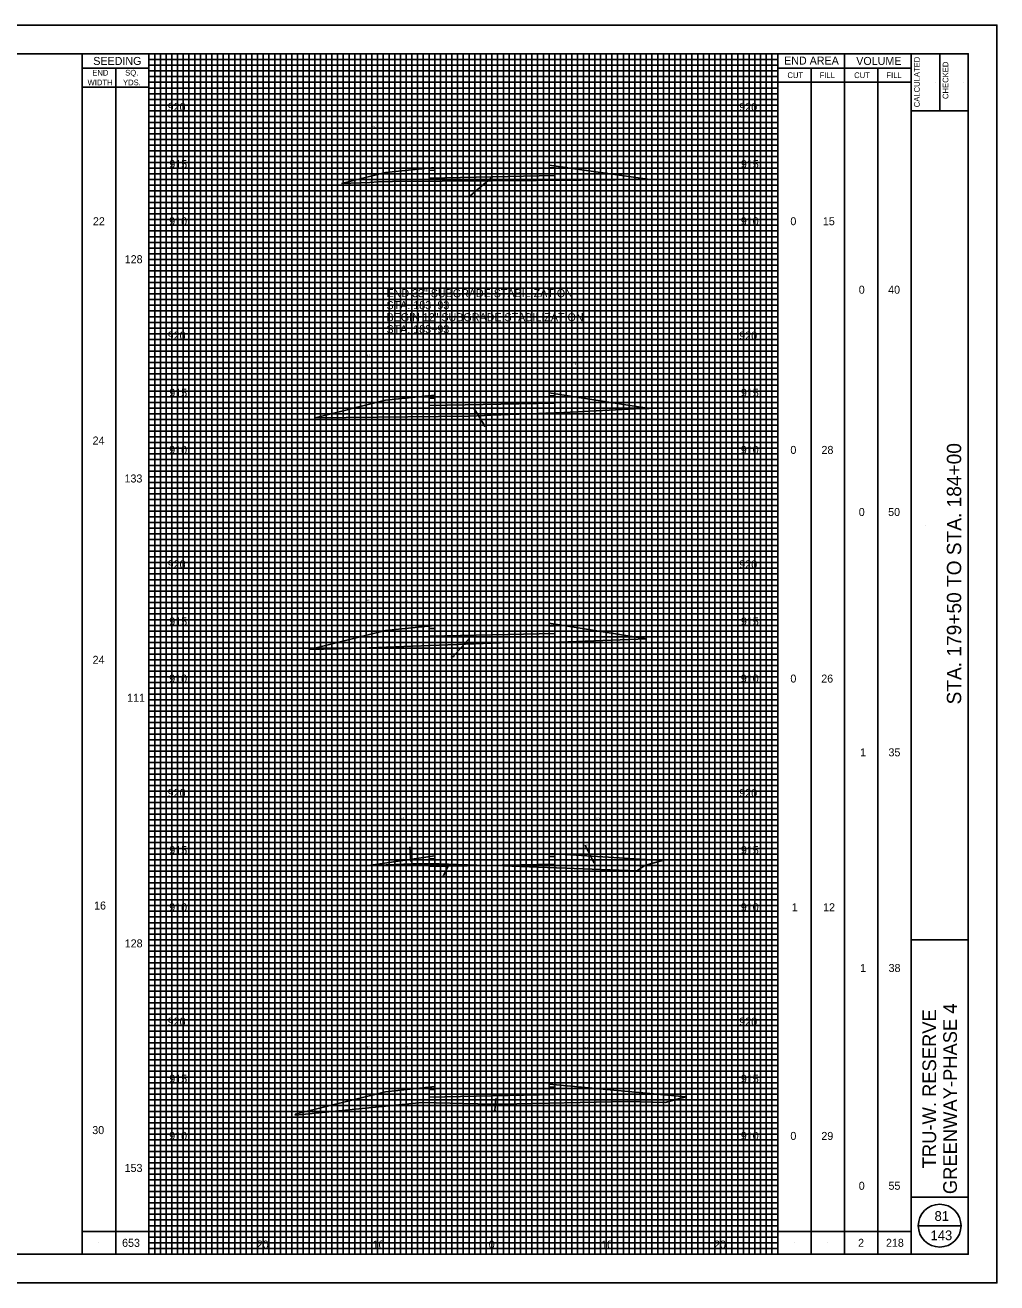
# Model space of a CAD drawing. Extents: x -73 to 160, y -2 to 1877.
# Drawn here: x 75 to 160, y 802.5 to 912.5 of the extents above; entities that cross this region are included whole.
import ezdxf

# ---------------------------------------------------------------- set-up
doc = ezdxf.new("R2010")
doc.units = 0
for name, color, linetype in [('DR_P_Flood_Boundary', 7, 'Continuous'), ('GK_Cells', 7, 'Continuous'), ('RD_X_Fence', 7, 'Continuous'), ('TX_X_5', 7, 'Continuous'), ('UT_P_Water_Cells', 7, 'Continuous'), ('XS_P_Pavt_Layers', 7, 'Continuous'), ('XS_P_Pavt_Surface', 7, 'Continuous'), ('XS_X_Ground_Line', 7, 'Continuous')]:
    doc.layers.add(name, color=color, linetype=linetype)

msp = doc.modelspace()

# ---------------------------------------------------------------- linework, layer by layer
at = {"layer": 'DR_P_Flood_Boundary'}
for p, q in [((90.83, 805), (90.83, 910)), ((95.83, 805), (95.83, 910)), ((100.83, 805), (100.83, 910)), ((105.83, 805), (105.83, 910)), ((110.83, 805), (110.83, 910)), ((115.83, 805), (115.83, 910)), ((120.83, 805), (120.83, 910)), ((125.83, 805), (125.83, 910)), ((130.83, 805), (130.83, 910)), ((135.83, 805), (135.83, 910)), ((85.83, 905), (140.83, 905)), ((85.83, 900), (140.83, 900)), ((85.83, 895), (140.83, 895)), ((85.83, 890), (140.83, 890)), ((85.83, 885), (140.83, 885)), ((85.83, 880), (140.83, 880)), ((85.83, 875), (140.83, 875)), ((85.83, 870), (140.83, 870)), ((85.83, 865), (140.83, 865)), ((85.83, 860), (140.83, 860)), ((85.83, 855), (140.83, 855)), ((85.83, 850), (140.83, 850)), ((85.83, 845), (140.83, 845)), ((85.83, 840), (140.83, 840)), ((85.83, 835), (140.83, 835)), ((85.83, 830), (140.83, 830)), ((85.83, 825), (140.83, 825)), ((85.83, 820), (140.83, 820)), ((85.83, 815), (140.83, 815)), ((85.83, 810), (140.83, 810))]:
    msp.add_line(p, q, dxfattribs=at)
at = {"layer": 'GK_Cells'}
for p, q in [((152.5, 805), (152.5, 910)), ((155, 910), (155, 905)), ((152.5, 905), (157.5, 905)), ((152.5, 832.5), (157.5, 832.5)), ((152.5, 810), (157.5, 810))]:
    msp.add_line(p, q, dxfattribs=at)
msp.add_lwpolyline([(0, 910), (157.5, 910), (157.5, 805), (0, 805)], close=True, dxfattribs=at)
at = {"layer": 'RD_X_Fence'}
for p, q in [((110.83, 900.06), (106.51, 899.61)), ((110.33, 899.8), (110.83, 899.81)), ((129.65, 899), (120.83, 900.26)), ((120.83, 900.01), (121.33, 900.02)), ((121.33, 900.02), (121.33, 899.35)), ((106.51, 899.61), (102.66, 898.65)), ((110.33, 899.13), (110.33, 899.8)), ((121.33, 899.35), (110.33, 899.13)), ((115.9, 899.25), (113.92, 897.58)), ((110.83, 880.14), (106.51, 879.7)), ((129.6, 878.96), (120.83, 880.34)), ((120.83, 880.09), (121.33, 880.1)), ((121.33, 880.1), (121.33, 879.44)), ((106.51, 879.7), (100.37, 878.16)), ((110.33, 879.88), (110.83, 879.89)), ((110.33, 879.22), (110.33, 879.88)), ((121.33, 879.44), (110.33, 879.22)), ((114.26, 878.99), (115.24, 877.41)), ((106.51, 859.55), (99.88, 857.89)), ((110.83, 859.99), (106.51, 859.55)), ((110.33, 859.73), (110.83, 859.74)), ((110.33, 859.07), (110.33, 859.73)), ((121.33, 859.29), (110.33, 859.07)), ((129.36, 858.83), (120.83, 860.19)), ((120.83, 859.94), (121.33, 859.95)), ((121.33, 859.95), (121.33, 859.29)), ((113.88, 858.88), (112.42, 857.25)), ((108.73, 839.35), (108.65, 840.6)), ((124.77, 839.22), (124, 840.79)), ((110.83, 839.84), (105.03, 839.01)), ((110.33, 839.58), (110.83, 839.59)), ((110.33, 839.16), (110.33, 839.58)), ((130.73, 839.44), (120.83, 840.04)), ((120.83, 840.04), (120.83, 839.93)), ((120.83, 839.93), (120.83, 839.79)), ((120.83, 839.79), (121.33, 839.8)), ((121.33, 839.8), (121.33, 839.13)), ((110.33, 839.16), (110.33, 838.91)), ((110.33, 838.91), (115.34, 839.01)), ((112.03, 839.03), (111.6, 838.1)), ((121.33, 839.13), (116.73, 839.04)), ((116.73, 839.04), (116.79, 838.98)), ((110.83, 819.67), (106.51, 819.22)), ((132.8, 818.77), (120.83, 819.87)), ((120.83, 819.62), (121.33, 819.63)), ((121.33, 819.63), (121.33, 818.96)), ((106.51, 819.22), (98.62, 817.25)), ((110.33, 819.41), (110.83, 819.42)), ((110.33, 818.74), (110.33, 819.41)), ((121.33, 818.96), (110.33, 818.74)), ((116.17, 818.62), (116.09, 817.56))]:
    msp.add_line(p, q, dxfattribs=at)
for points in [[(110.83, 899.81), (110.83, 899.95), (110.83, 900.06)], [(120.83, 900.26), (120.83, 900.15), (120.83, 900.01)], [(102.66, 898.65), (105.14, 898.74), (105.88, 898.8), (107.13, 898.82), (115.83, 898.88), (123.61, 898.94), (129.65, 899)], [(110.83, 879.89), (110.83, 880.04), (110.83, 880.14)], [(120.83, 880.34), (120.83, 880.24), (120.83, 880.09)], [(100.37, 878.16), (113.88, 878.3), (115.83, 878.38), (122.11, 878.63), (128.32, 878.95), (129.6, 878.96)], [(110.83, 859.74), (110.83, 859.89), (110.83, 859.99)], [(120.83, 860.19), (120.83, 860.09), (120.83, 859.94)], [(99.88, 857.89), (103.52, 857.98), (115.83, 858.45), (118.07, 858.54), (120.92, 858.51), (129.36, 858.83)], [(110.83, 839.59), (110.83, 839.73), (110.83, 839.84)], [(116.79, 838.98), (128.51, 838.53), (129.22, 838.99), (130.73, 839.44)], [(105.03, 839.01), (108.89, 839.15), (110.33, 839.16)], [(115.34, 839.01), (111.23, 839.16), (110.33, 839.16)], [(110.83, 819.42), (110.83, 819.56), (110.83, 819.67)], [(120.83, 819.87), (120.83, 819.76), (120.83, 819.62)], [(98.65, 817.16), (109.72, 818.27), (115.83, 818.13), (116.62, 818.12), (127.71, 818.37), (130.99, 818.26), (132.8, 818.77)], [(98.62, 817.25), (98.65, 817.16)]]:
    msp.add_lwpolyline(points, dxfattribs=at)
at = {"layer": 'TX_X_5'}
msp.add_lwpolyline([(-10, 802.5), (160, 802.5), (160, 912.5), (-10, 912.5)], close=True, dxfattribs=at)
at = {"layer": 'UT_P_Water_Cells'}
for p, q in [((86.33, 805), (86.33, 910)), ((86.83, 805), (86.83, 910)), ((87.33, 805), (87.33, 910)), ((87.83, 805), (87.83, 910)), ((88.33, 805), (88.33, 910)), ((88.83, 805), (88.83, 910)), ((89.33, 805), (89.33, 910)), ((89.83, 805), (89.83, 910)), ((90.33, 805), (90.33, 910)), ((91.33, 805), (91.33, 910)), ((91.83, 805), (91.83, 910)), ((92.33, 805), (92.33, 910)), ((92.83, 805), (92.83, 910)), ((93.33, 805), (93.33, 910)), ((93.83, 805), (93.83, 910)), ((94.33, 805), (94.33, 910)), ((94.83, 805), (94.83, 910)), ((95.33, 805), (95.33, 910)), ((96.33, 805), (96.33, 910)), ((96.83, 805), (96.83, 910)), ((97.33, 805), (97.33, 910)), ((97.83, 805), (97.83, 910)), ((98.33, 805), (98.33, 910)), ((98.83, 805), (98.83, 910)), ((99.33, 805), (99.33, 910)), ((99.83, 805), (99.83, 910)), ((100.33, 805), (100.33, 910)), ((101.33, 805), (101.33, 910)), ((101.83, 805), (101.83, 910)), ((102.33, 805), (102.33, 910)), ((102.83, 805), (102.83, 910)), ((103.33, 805), (103.33, 910)), ((103.83, 805), (103.83, 910)), ((104.33, 805), (104.33, 910)), ((104.83, 805), (104.83, 910)), ((105.33, 805), (105.33, 910)), ((106.33, 805), (106.33, 910)), ((106.83, 805), (106.83, 910)), ((107.33, 805), (107.33, 910)), ((107.83, 805), (107.83, 910)), ((108.33, 805), (108.33, 910)), ((108.83, 805), (108.83, 910)), ((109.33, 805), (109.33, 910)), ((109.83, 805), (109.83, 910)), ((110.33, 805), (110.33, 910)), ((111.33, 805), (111.33, 910)), ((111.83, 805), (111.83, 910)), ((112.33, 805), (112.33, 910)), ((112.83, 805), (112.83, 910)), ((113.33, 805), (113.33, 910)), ((113.83, 805), (113.83, 910)), ((114.33, 805), (114.33, 910)), ((114.83, 805), (114.83, 910)), ((115.33, 805), (115.33, 910)), ((116.33, 805), (116.33, 910)), ((116.83, 805), (116.83, 910)), ((117.33, 805), (117.33, 910)), ((117.83, 805), (117.83, 910)), ((118.33, 805), (118.33, 910)), ((118.83, 805), (118.83, 910)), ((119.33, 805), (119.33, 910)), ((119.83, 805), (119.83, 910)), ((120.33, 805), (120.33, 910)), ((121.33, 805), (121.33, 910)), ((121.83, 805), (121.83, 910)), ((122.33, 805), (122.33, 910)), ((122.83, 805), (122.83, 910)), ((123.33, 805), (123.33, 910)), ((123.83, 805), (123.83, 910)), ((124.33, 805), (124.33, 910)), ((124.83, 805), (124.83, 910)), ((125.33, 805), (125.33, 910)), ((126.33, 805), (126.33, 910)), ((126.83, 805), (126.83, 910)), ((127.33, 805), (127.33, 910)), ((127.83, 805), (127.83, 910)), ((128.33, 805), (128.33, 910)), ((128.83, 805), (128.83, 910)), ((129.33, 805), (129.33, 910)), ((129.83, 805), (129.83, 910)), ((130.33, 805), (130.33, 910)), ((131.33, 805), (131.33, 910)), ((131.83, 805), (131.83, 910)), ((132.33, 805), (132.33, 910)), ((132.83, 805), (132.83, 910)), ((133.33, 805), (133.33, 910)), ((133.83, 805), (133.83, 910)), ((134.33, 805), (134.33, 910)), ((134.83, 805), (134.83, 910)), ((135.33, 805), (135.33, 910)), ((136.33, 805), (136.33, 910)), ((136.83, 805), (136.83, 910)), ((137.33, 805), (137.33, 910)), ((137.83, 805), (137.83, 910)), ((138.33, 805), (138.33, 910)), ((138.83, 805), (138.83, 910)), ((139.33, 805), (139.33, 910)), ((139.83, 805), (139.83, 910)), ((140.33, 805), (140.33, 910)), ((85.83, 909.5), (140.83, 909.5)), ((85.83, 909), (140.83, 909)), ((85.83, 908.5), (140.83, 908.5)), ((85.83, 908), (140.83, 908)), ((85.83, 907.5), (140.83, 907.5)), ((85.83, 907), (140.83, 907)), ((85.83, 906.5), (140.83, 906.5)), ((85.83, 906), (140.83, 906)), ((85.83, 905.5), (140.83, 905.5)), ((85.83, 904.5), (140.83, 904.5)), ((85.83, 904), (140.83, 904)), ((85.83, 903.5), (140.83, 903.5)), ((85.83, 903), (140.83, 903)), ((85.83, 902.5), (140.83, 902.5)), ((85.83, 902), (140.83, 902)), ((85.83, 901.5), (140.83, 901.5)), ((85.83, 901), (140.83, 901)), ((85.83, 900.5), (140.83, 900.5)), ((85.83, 899.5), (140.83, 899.5)), ((85.83, 899), (140.83, 899)), ((85.83, 898.5), (140.83, 898.5)), ((85.83, 898), (140.83, 898)), ((85.83, 897.5), (140.83, 897.5)), ((85.83, 897), (140.83, 897)), ((85.83, 896.5), (140.83, 896.5)), ((85.83, 896), (140.83, 896)), ((85.83, 895.5), (140.83, 895.5)), ((85.83, 894.5), (140.83, 894.5)), ((85.83, 894), (140.83, 894)), ((85.83, 893.5), (140.83, 893.5)), ((85.83, 893), (140.83, 893)), ((85.83, 892.5), (140.83, 892.5)), ((85.83, 892), (140.83, 892)), ((85.83, 891.5), (140.83, 891.5)), ((85.83, 891), (140.83, 891)), ((85.83, 890.5), (140.83, 890.5)), ((85.83, 889.5), (140.83, 889.5)), ((85.83, 889), (140.83, 889)), ((85.83, 888.5), (140.83, 888.5)), ((85.83, 888), (140.83, 888)), ((85.83, 887.5), (140.83, 887.5)), ((85.83, 887), (140.83, 887)), ((85.83, 886.5), (140.83, 886.5)), ((85.83, 886), (140.83, 886)), ((85.83, 885.5), (140.83, 885.5)), ((85.83, 884.5), (140.83, 884.5)), ((85.83, 884), (140.83, 884)), ((85.83, 883.5), (140.83, 883.5)), ((85.83, 883), (140.83, 883)), ((85.83, 882.5), (140.83, 882.5)), ((85.83, 882), (140.83, 882)), ((85.83, 881.5), (140.83, 881.5)), ((85.83, 881), (140.83, 881)), ((85.83, 880.5), (140.83, 880.5)), ((85.83, 879.5), (140.83, 879.5)), ((85.83, 879), (140.83, 879)), ((85.83, 878.5), (140.83, 878.5)), ((85.83, 878), (140.83, 878)), ((85.83, 877.5), (140.83, 877.5)), ((85.83, 877), (140.83, 877)), ((85.83, 876.5), (140.83, 876.5)), ((85.83, 876), (140.83, 876)), ((85.83, 875.5), (140.83, 875.5)), ((85.83, 874.5), (140.83, 874.5)), ((85.83, 874), (140.83, 874)), ((85.83, 873.5), (140.83, 873.5)), ((85.83, 873), (140.83, 873)), ((85.83, 872.5), (140.83, 872.5)), ((85.83, 872), (140.83, 872)), ((85.83, 871.5), (140.83, 871.5)), ((85.83, 871), (140.83, 871)), ((85.83, 870.5), (140.83, 870.5)), ((85.83, 869.5), (140.83, 869.5)), ((85.83, 869), (140.83, 869)), ((85.83, 868.5), (140.83, 868.5)), ((85.83, 868), (140.83, 868)), ((85.83, 867.5), (140.83, 867.5)), ((85.83, 867), (140.83, 867)), ((85.83, 866.5), (140.83, 866.5)), ((85.83, 866), (140.83, 866)), ((85.83, 865.5), (140.83, 865.5)), ((85.83, 864.5), (140.83, 864.5)), ((85.83, 864), (140.83, 864)), ((85.83, 863.5), (140.83, 863.5)), ((85.83, 863), (140.83, 863)), ((85.83, 862.5), (140.83, 862.5)), ((85.83, 862), (140.83, 862)), ((85.83, 861.5), (140.83, 861.5)), ((85.83, 861), (140.83, 861)), ((85.83, 860.5), (140.83, 860.5)), ((85.83, 859.5), (140.83, 859.5)), ((85.83, 859), (140.83, 859)), ((85.83, 858.5), (140.83, 858.5)), ((85.83, 858), (140.83, 858)), ((85.83, 857.5), (140.83, 857.5)), ((85.83, 857), (140.83, 857)), ((85.83, 856.5), (140.83, 856.5)), ((85.83, 856), (140.83, 856)), ((85.83, 855.5), (140.83, 855.5)), ((85.83, 854.5), (140.83, 854.5)), ((85.83, 854), (140.83, 854)), ((85.83, 853.5), (140.83, 853.5)), ((85.83, 853), (140.83, 853)), ((85.83, 852.5), (140.83, 852.5)), ((85.83, 852), (140.83, 852)), ((85.83, 851.5), (140.83, 851.5)), ((85.83, 851), (140.83, 851)), ((85.83, 850.5), (140.83, 850.5)), ((85.83, 849.5), (140.83, 849.5)), ((85.83, 849), (140.83, 849)), ((85.83, 848.5), (140.83, 848.5)), ((85.83, 848), (140.83, 848)), ((85.83, 847.5), (140.83, 847.5)), ((85.83, 847), (140.83, 847)), ((85.83, 846.5), (140.83, 846.5)), ((85.83, 846), (140.83, 846)), ((85.83, 845.5), (140.83, 845.5)), ((85.83, 844.5), (140.83, 844.5)), ((85.83, 844), (140.83, 844)), ((85.83, 843.5), (140.83, 843.5)), ((85.83, 843), (140.83, 843)), ((85.83, 842.5), (140.83, 842.5)), ((85.83, 842), (140.83, 842)), ((85.83, 841.5), (140.83, 841.5)), ((85.83, 841), (140.83, 841)), ((85.83, 840.5), (140.83, 840.5)), ((85.83, 839.5), (140.83, 839.5)), ((85.83, 839), (140.83, 839)), ((85.83, 838.5), (140.83, 838.5)), ((85.83, 838), (140.83, 838)), ((85.83, 837.5), (140.83, 837.5)), ((85.83, 837), (140.83, 837)), ((85.83, 836.5), (140.83, 836.5)), ((85.83, 836), (140.83, 836)), ((85.83, 835.5), (140.83, 835.5)), ((85.83, 834.5), (140.83, 834.5)), ((85.83, 834), (140.83, 834)), ((85.83, 833.5), (140.83, 833.5)), ((85.83, 833), (140.83, 833)), ((85.83, 832.5), (140.83, 832.5)), ((85.83, 832), (140.83, 832)), ((85.83, 831.5), (140.83, 831.5)), ((85.83, 831), (140.83, 831)), ((85.83, 830.5), (140.83, 830.5)), ((85.83, 829.5), (140.83, 829.5)), ((85.83, 829), (140.83, 829)), ((85.83, 828.5), (140.83, 828.5)), ((85.83, 828), (140.83, 828)), ((85.83, 827.5), (140.83, 827.5)), ((85.83, 827), (140.83, 827)), ((85.83, 826.5), (140.83, 826.5)), ((85.83, 826), (140.83, 826)), ((85.83, 825.5), (140.83, 825.5)), ((85.83, 824.5), (140.83, 824.5)), ((85.83, 824), (140.83, 824)), ((85.83, 823.5), (140.83, 823.5)), ((85.83, 823), (140.83, 823)), ((85.83, 822.5), (140.83, 822.5)), ((85.83, 822), (140.83, 822)), ((85.83, 821.5), (140.83, 821.5)), ((85.83, 821), (140.83, 821)), ((85.83, 820.5), (140.83, 820.5)), ((85.83, 819.5), (140.83, 819.5)), ((85.83, 819), (140.83, 819)), ((85.83, 818.5), (140.83, 818.5)), ((85.83, 818), (140.83, 818)), ((85.83, 817.5), (140.83, 817.5)), ((85.83, 817), (140.83, 817)), ((85.83, 816.5), (140.83, 816.5)), ((85.83, 816), (140.83, 816)), ((85.83, 815.5), (140.83, 815.5)), ((85.83, 814.5), (140.83, 814.5)), ((85.83, 814), (140.83, 814)), ((85.83, 813.5), (140.83, 813.5)), ((85.83, 813), (140.83, 813)), ((85.83, 812.5), (140.83, 812.5)), ((85.83, 812), (140.83, 812)), ((85.83, 811.5), (140.83, 811.5)), ((85.83, 811), (140.83, 811)), ((85.83, 810.5), (140.83, 810.5)), ((85.83, 809.5), (140.83, 809.5)), ((85.83, 809), (140.83, 809)), ((85.83, 808.5), (140.83, 808.5)), ((85.83, 808), (140.83, 808)), ((85.83, 807.5), (140.83, 807.5)), ((85.83, 807), (140.83, 807)), ((85.83, 806.5), (140.83, 806.5)), ((85.83, 806), (140.83, 806)), ((85.83, 805.5), (140.83, 805.5))]:
    msp.add_line(p, q, dxfattribs=at)
at = {"layer": 'XS_X_Ground_Line'}
for p, q in [((80, 805), (80, 910)), ((85.83, 805), (85.83, 910)), ((140.83, 805), (140.83, 910)), ((146.67, 805), (146.67, 910)), ((85.83, 908.75), (80, 908.75)), ((82.92, 805), (82.92, 908.75)), ((140.83, 908.75), (152.5, 908.75)), ((143.75, 805), (143.75, 908.75)), ((149.58, 805), (149.58, 908.75)), ((154.6, 907.52), (154.6, 907.52)), ((157.1, 907.52), (157.1, 907.52)), ((85.83, 907.08), (80, 907.08)), ((140.83, 907.5), (152.5, 907.5)), ((153.75, 868.75), (153.75, 868.75)), ((156.26, 868.75), (156.26, 868.75)), ((155, 821.46), (155, 821.46)), ((153.12, 807.5), (156.88, 807.5)), ((155, 807.92), (155, 807.92)), ((80, 807), (85.83, 807)), ((140.83, 807), (152.5, 807)), ((81.46, 806.03), (81.46, 806.03)), ((84.37, 806.03), (84.37, 806.03)), ((142.29, 806), (142.29, 806)), ((145.21, 806), (145.21, 806)), ((148.12, 806), (148.12, 806)), ((151.04, 806), (151.04, 806)), ((155, 806.23), (155, 806.23))]:
    msp.add_line(p, q, dxfattribs=at)
msp.add_circle((155, 807.5), 1.87, dxfattribs=at)

# ---------------------------------------------------------------- texts
at = {"layer": 'RD_X_Fence'}
for s, p in [('4.0', (105.38, 903.57)), ('4.3', (108.51, 903.47)), ('9.3', (120.12, 903.92)), ('14.8', (113.74, 897.51)), ('6.3', (104.89, 883.54)), ('4.3', (108.63, 883.17)), ('8.9', (123.08, 882.77)), ('28.0', (115.03, 877.34)), ('8.6', (123.3, 862.51)), ('6.8', (104.86, 862.13)), ('4.3', (108.21, 862.06)), ('25.8', (112.21, 857.18)), ('5.9', (107.89, 843.08)), ('9.9', (124.96, 843.04)), ('1.6', (108.53, 840.53)), ('10.0', (123.81, 840.72)), ('0.7', (111.45, 838.03)), ('9.5', (104.89, 823.06)), ('4.3', (108.2, 823.06)), ('12.0', (123.87, 822.98)), ('28.9', (115.89, 817.49))]:
    msp.add_text(s, height=0.14, dxfattribs=at).set_placement(p)
at = {"layer": 'XS_P_Pavt_Layers'}
for s, p in [('81', (154.55, 807.92)), ('143', (154.2, 806.23))]:
    msp.add_text(s, height=0.85, dxfattribs=at).set_placement(p)
at = {"layer": 'XS_P_Pavt_Surface'}
for s, p in [('920', (87.47, 905)), ('920', (137.47, 905)), ('915', (87.61, 900)), ('915', (137.61, 900)), ('22', (80.93, 895)), ('910', (87.6, 895)), ('910', (137.6, 895)), ('0', (141.94, 895)), ('15', (144.78, 895)), ('128', (83.71, 891.68)), ('END 33" SUBGRADE STABILIZATION', (106.61, 888.71)), ('0', (147.92, 889.01)), ('40', (150.49, 889.01)), ('STA. 183+93', (106.61, 887.66)), ('BEGIN 12" SUBGRADE STABILIZATION', (106.61, 886.61)), ('920', (87.47, 885)), ('STA. 183+93', (106.61, 885.56)), ('920', (137.47, 885)), ('915', (87.61, 880)), ('915', (137.61, 880)), ('24', (80.9, 875.82)), ('910', (87.6, 875)), ('910', (137.6, 875)), ('0', (141.94, 875)), ('28', (144.66, 875)), ('133', (83.69, 872.5)), ('0', (147.92, 869.57)), ('50', (150.49, 869.57)), ('920', (87.47, 865)), ('920', (137.47, 865)), ('915', (87.61, 860)), ('915', (137.61, 860)), ('24', (80.9, 856.64)), ('910', (87.6, 855)), ('910', (137.6, 855)), ('0', (141.94, 855)), ('26', (144.64, 855)), ('111', (83.92, 853.32)), ('1', (148.04, 848.55)), ('35', (150.52, 848.55)), ('920', (87.47, 845)), ('920', (137.47, 845)), ('915', (87.61, 840)), ('915', (137.61, 840)), ('16', (81.03, 835.15)), ('910', (87.6, 835)), ('910', (137.6, 835)), ('1', (142.06, 835)), ('12', (144.8, 835)), ('128', (83.71, 831.84)), ('1', (148.04, 829.69)), ('38', (150.53, 829.69)), ('920', (87.47, 825)), ('920', (137.47, 825)), ('915', (87.61, 820)), ('915', (137.61, 820)), ('30', (80.87, 815.51)), ('910', (87.6, 815)), ('910', (137.6, 815)), ('0', (141.94, 815)), ('29', (144.65, 815)), ('153', (83.7, 812.2)), ('0', (147.92, 810.64)), ('55', (150.52, 810.64)), ('653', (83.48, 805.65)), ('2', (147.86, 805.65)), ('218', (150.3, 805.65)), ('20', (95.26, 805.5)), ('10', (105.39, 805.5)), ('0', (115.55, 805.5)), ('0', (115.55, 805.5)), ('10', (125.39, 805.5)), ('20', (135.26, 805.5))]:
    msp.add_text(s, height=0.7, dxfattribs=at).set_placement(p)
for s, p in [('TRU-W. RESERVE', (154.69, 812.52)), ('GREENWAY-PHASE 4', (156.51, 810.26))]:
    msp.add_text(s, height=1.2, rotation=90, dxfattribs=at).set_placement(p)
at = {"layer": 'XS_X_Ground_Line'}
for s, height, p in [('SEEDING', 0.7, (80.96, 909.02)), ('END AREA', 0.7, (141.39, 909.05)), ('VOLUME', 0.7, (147.7, 909.02)), ('WIDTH', 0.5, (80.46, 907.24)), ('END', 0.5, (80.87, 908.09)), ('YDS.', 0.5, (83.56, 907.24)), ('SQ.', 0.5, (83.75, 908.09)), ('CUT', 0.5, (141.68, 907.87)), ('FILL', 0.5, (144.5, 907.87)), ('CUT', 0.5, (147.52, 907.87)), ('FILL', 0.5, (150.34, 907.87)), ('143', 0.85, (154.2, 806.23))]:
    msp.add_text(s, height=height, dxfattribs=at).set_placement(p)
for s, height, p in [('CALCULATED', 0.5, (153.26, 905.32)), ('CHECKED', 0.5, (155.76, 906.04)), ('STA. 179+50 TO STA. 184+00', 1.25, (156.88, 853.09))]:
    msp.add_text(s, height=height, rotation=90, dxfattribs=at).set_placement(p)

doc.saveas('drawing.dxf')
